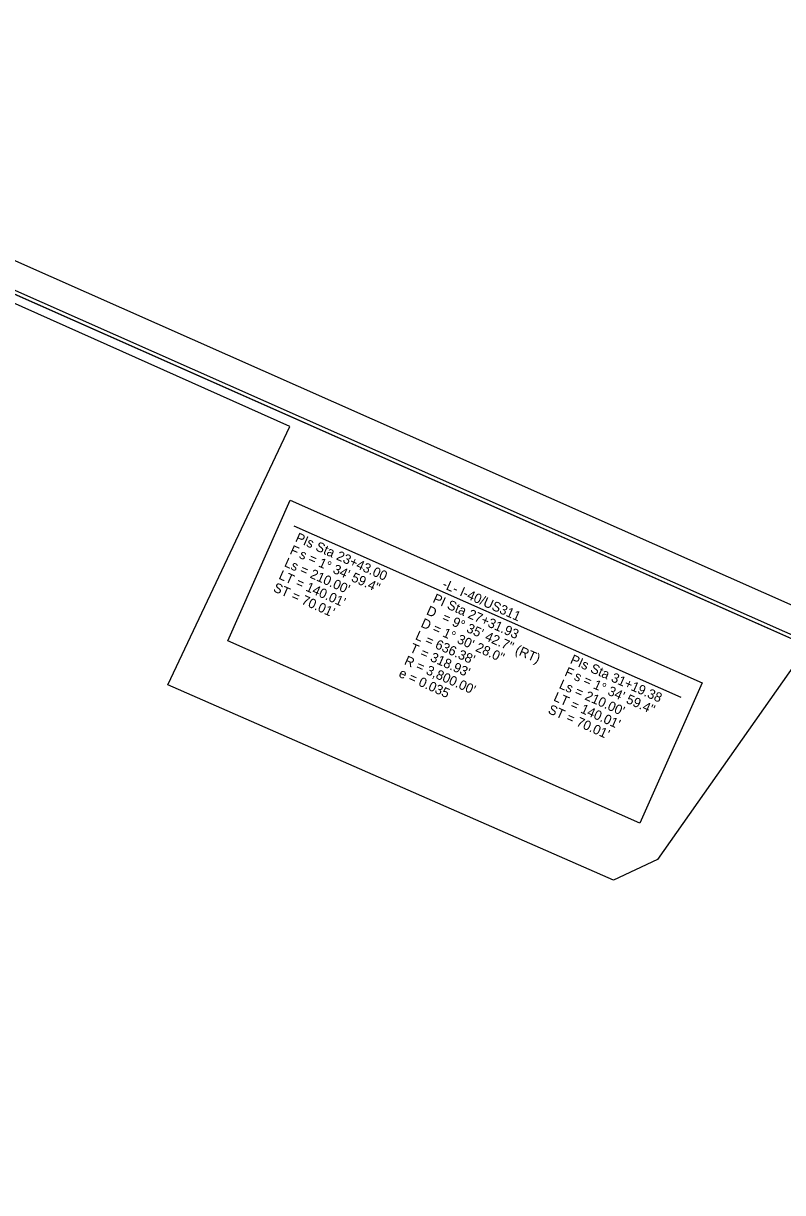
# Model space of a CAD drawing. Extents: x 1637682 to 2864602, y 842496 to 973236.
# Drawn here: x 1638524 to 1639080, y 843324 to 844179 of the extents above; entities that cross this region are included whole.
import ezdxf

# ---------------------------------------------------------------- set-up
doc = ezdxf.new("R2010")
doc.units = 0
for name, color, linetype in [('Prop Horizontal Alignment Curve and Spiral Data', 7, 'Continuous'), ('Sheet Clip Boundary CELL', 7, 'Continuous'), ('Sheet Plan CELL', 7, 'Continuous'), ('Sheet Plot Border Inside CELL', 7, 'Continuous'), ('Sheet Plot Border Outside CELL', 7, 'Continuous')]:
    doc.layers.add(name, color=color, linetype=linetype)

msp = doc.modelspace()

# ---------------------------------------------------------------- linework, layer by layer
at = {"layer": 'Prop Horizontal Alignment Curve and Spiral Data'}
for p, q in [((1638673.88, 843727.68), (1638719.45, 843830.45)), ((1638719.45, 843830.45), (1639020.89, 843696.79)), ((1638722.11, 843811.77), (1639005.26, 843686.22)), ((1638975.32, 843594.02), (1638673.88, 843727.68)), ((1639020.89, 843696.79), (1638975.32, 843594.02))]:
    msp.add_line(p, q, dxfattribs=at)
at = {"layer": 'Sheet Clip Boundary CELL'}
msp.add_lwpolyline([(1638095.26, 843695.55), (1638010.34, 843303.19), (1637949.73, 843324.57), (1637886.34, 843167.39), (1638760.91, 842777.56), (1638750.92, 842749.91), (1638861.21, 842700.69), (1639015.67, 842665.82), (1639189.46, 842589.52), (1639522.76, 843341.19), (1639380.4, 843404.31), (1639446.06, 843552.39), (1639089.07, 843710.68), (1638988.3, 843567.43), (1638956.05, 843552.43), (1638629.84, 843695.47), (1638719.07, 843884.38), (1638267, 844086.34)], close=True, dxfattribs=at)
at = {"layer": 'Sheet Plan CELL'}
for points in [[(1639640.56, 843483.39), (1638269.28, 844091.43), (1637843.67, 843131.56), (1639214.92, 842523.53)], [(1637843.67, 843131.56), (1638269.25, 844091.42), (1639457.67, 843564.51), (1639396.85, 843427.32), (1639579.71, 843346.22), (1639214.92, 842523.53)]]:
    msp.add_lwpolyline(points, close=True, dxfattribs=at)
at = {"layer": 'Sheet Plot Border Inside CELL'}
msp.add_lwpolyline([(1637702.34, 843191.48), (1639225.33, 842516.19), (1639652.97, 843480.61), (1638129.98, 844155.92)], close=True, dxfattribs=at)
at = {"layer": 'Sheet Plot Border Outside CELL'}
msp.add_lwpolyline([(1637682.35, 843178.46), (1639221.34, 842496.06), (1639665.19, 843497.07), (1638126.2, 844179.47)], close=True, dxfattribs=at)
msp.add_lwpolyline([(1637682.35, 843178.46), (1639221.34, 842496.06), (1639665.19, 843497.07), (1638126.2, 844179.47)], close=True, dxfattribs=at)

# ---------------------------------------------------------------- texts
at = {"layer": 'Prop Horizontal Alignment Curve and Spiral Data'}
for s, p in [('PIs Sta 23+43.00', (1638722.62, 843800.6)), ('F', (1638718.57, 843791.46)), ("Ls = 210.00'", (1638714.52, 843782.32)), ('s = 1%%d 34\' 59.4"', (1638725.44, 843788.42)), ("LT = 140.01'", (1638710.46, 843773.18)), ('-L- I-40/US311', (1638830.09, 843766.63)), ("ST = 70.01'", (1638706.41, 843764.04)), ('PI Sta 27+31.93', (1638823.18, 843756.02)), ('D', (1638818.51, 843747.15)), ('= 9%%d 35\' 42.7" (RT)', (1638829.9, 843742.23)), ('D = 1%%d 30\' 28.0"', (1638814.46, 843738.01)), ("L = 636.38'", (1638810.4, 843728.86)), ("T = 318.93'", (1638806.35, 843719.72)), ("R = 3,800.00'", (1638802.3, 843710.58)), ('PIs Sta 31+19.38', (1638923.74, 843711.43)), ('e = 0.035', (1638798.24, 843701.44)), ('F', (1638919.69, 843702.29)), ('s = 1%%d 34\' 59.4"', (1638926.56, 843699.24)), ("Ls = 210.00'", (1638915.63, 843693.15)), ("LT = 140.01'", (1638911.58, 843684)), ("ST = 70.01'", (1638907.53, 843674.86))]:
    msp.add_text(s, height=7, rotation=336.08714, dxfattribs=at).set_placement(p)

doc.saveas('drawing.dxf')
